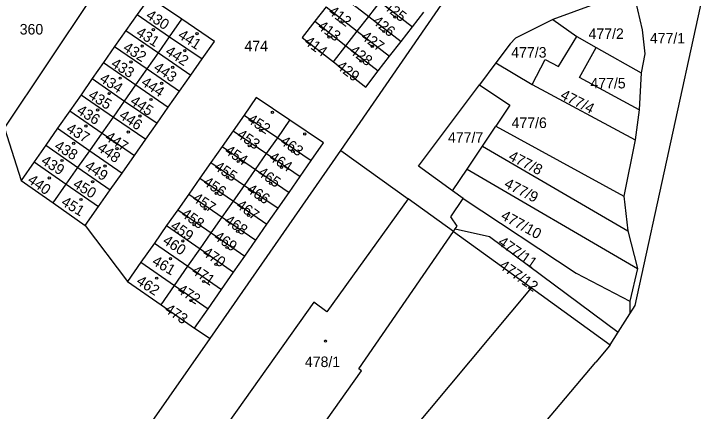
# Model space of a CAD drawing. Extents: x -558358 to -557517, y -1073786 to -1073189.
# Drawn here: x -557909.7 to -557797.9, y -1073407.2 to -1073343.1 of the extents above; entities that cross this region are included whole.
import ezdxf

# ---------------------------------------------------------------- set-up
doc = ezdxf.new("R2010")
doc.units = 0
for name, color, linetype in [('Hranice parcel', 7, 'Continuous'), ('Parcelní čísla', 7, 'Continuous'), ('Značky budov', 7, 'Continuous')]:
    doc.layers.add(name, color=color, linetype=linetype)

msp = doc.modelspace()

# ---------------------------------------------------------------- linework, layer by layer
at = {"layer": 'Hranice parcel'}
for p, q in [((-557911.2, -1073361.51), (-557892.99, -1073334.25)), ((-557809.37, -1073390.13), (-557797.89, -1073337.76)), ((-557809.74, -1073339.14), (-557822.65, -1073343.99)), ((-557857.41, -1073339.54), (-557852.37, -1073343.47)), ((-557852.37, -1073343.47), (-557850.52, -1073341.11)), ((-557850.52, -1073341.11), (-557845.33, -1073345.15)), ((-557859.26, -1073341.9), (-557861.1, -1073344.25)), ((-557859.26, -1073341.9), (-557854.22, -1073345.83)), ((-557845.33, -1073345.15), (-557843.49, -1073342.78)), ((-557889.79, -1073343.18), (-557891.6, -1073345.76)), ((-557889.79, -1073343.18), (-557884.54, -1073346.76)), ((-557884.54, -1073346.76), (-557882.54, -1073343.92)), ((-557854.22, -1073345.83), (-557852.37, -1073343.47)), ((-557852.37, -1073343.47), (-557847.16, -1073347.52)), ((-557861.1, -1073344.25), (-557856.06, -1073348.19)), ((-557822.65, -1073343.99), (-557818.8, -1073346.73)), ((-557891.6, -1073345.76), (-557893.41, -1073348.34)), ((-557891.6, -1073345.76), (-557886.35, -1073349.35)), ((-557856.06, -1073348.19), (-557854.22, -1073345.83)), ((-557854.22, -1073345.83), (-557849, -1073349.9)), ((-557847.16, -1073347.52), (-557845.33, -1073345.15)), ((-557886.35, -1073349.35), (-557884.54, -1073346.76)), ((-557884.54, -1073346.76), (-557879.29, -1073350.34)), ((-557818.8, -1073346.73), (-557815.63, -1073348.5)), ((-557893.41, -1073348.34), (-557895.22, -1073350.93)), ((-557893.41, -1073348.34), (-557888.17, -1073351.94)), ((-557858.09, -1073350.78), (-557856.06, -1073348.19)), ((-557856.06, -1073348.19), (-557850.83, -1073352.27)), ((-557849, -1073349.9), (-557847.16, -1073347.52)), ((-557888.17, -1073351.94), (-557886.35, -1073349.35)), ((-557886.35, -1073349.35), (-557881.11, -1073352.93)), ((-557815.63, -1073348.5), (-557808.41, -1073352.55)), ((-557881.11, -1073352.93), (-557879.29, -1073350.34)), ((-557850.83, -1073352.27), (-557849, -1073349.9)), ((-557895.22, -1073350.93), (-557897.03, -1073353.51)), ((-557895.22, -1073350.93), (-557889.99, -1073354.53)), ((-557831.83, -1073350.97), (-557834.5, -1073354.52)), ((-557831.83, -1073350.97), (-557825.97, -1073354.44)), ((-557889.99, -1073354.53), (-557888.17, -1073351.94)), ((-557888.17, -1073351.94), (-557882.93, -1073355.52)), ((-557808.41, -1073352.55), (-557808.71, -1073358.52)), ((-557897.03, -1073353.51), (-557898.84, -1073356.1)), ((-557897.03, -1073353.51), (-557891.81, -1073357.12)), ((-557882.93, -1073355.52), (-557881.11, -1073352.93)), ((-557891.81, -1073357.12), (-557889.99, -1073354.53)), ((-557889.99, -1073354.53), (-557884.75, -1073358.12)), ((-557825.97, -1073354.44), (-557809.38, -1073363.37)), ((-557898.84, -1073356.1), (-557900.65, -1073358.68)), ((-557898.84, -1073356.1), (-557893.62, -1073359.71)), ((-557884.75, -1073358.12), (-557882.93, -1073355.52)), ((-557893.62, -1073359.71), (-557891.81, -1073357.12)), ((-557891.81, -1073357.12), (-557886.57, -1073360.71)), ((-557886.57, -1073360.71), (-557884.75, -1073358.12)), ((-557900.65, -1073358.68), (-557902.64, -1073361.52)), ((-557900.65, -1073358.68), (-557895.44, -1073362.3)), ((-557872.5, -1073359.38), (-557874.29, -1073361.93)), ((-557872.5, -1073359.38), (-557867.08, -1073363.05)), ((-557808.71, -1073358.52), (-557809.38, -1073363.37)), ((-557895.44, -1073362.3), (-557893.62, -1073359.71)), ((-557893.62, -1073359.71), (-557888.4, -1073363.3)), ((-557867.08, -1073363.05), (-557865.11, -1073360.23)), ((-557911.2, -1073361.51), (-557908.52, -1073369.92)), ((-557902.64, -1073361.52), (-557904.53, -1073364.22)), ((-557902.64, -1073361.52), (-557897.44, -1073365.14)), ((-557888.4, -1073363.3), (-557886.57, -1073360.71)), ((-557834.02, -1073364.39), (-557831.83, -1073361.18)), ((-557831.83, -1073361.18), (-557811.19, -1073372.48)), ((-557897.44, -1073365.14), (-557895.44, -1073362.3)), ((-557895.44, -1073362.3), (-557890.22, -1073365.89)), ((-557874.29, -1073361.93), (-557876.07, -1073364.48)), ((-557874.29, -1073361.93), (-557868.87, -1073365.61)), ((-557890.22, -1073365.89), (-557888.4, -1073363.3)), ((-557868.87, -1073365.61), (-557867.08, -1073363.05)), ((-557867.08, -1073363.05), (-557861.66, -1073366.72)), ((-557809.38, -1073363.37), (-557811.19, -1073372.48)), ((-557904.53, -1073364.22), (-557906.42, -1073366.92)), ((-557904.53, -1073364.22), (-557899.34, -1073367.84)), ((-557899.34, -1073367.84), (-557897.44, -1073365.14)), ((-557897.44, -1073365.14), (-557892.22, -1073368.74)), ((-557877.97, -1073395.43), (-557856.89, -1073365.11)), ((-557876.07, -1073364.48), (-557877.86, -1073367.03)), ((-557876.07, -1073364.48), (-557870.66, -1073368.17)), ((-557856.89, -1073365.11), (-557845.99, -1073372.93)), ((-557836.47, -1073368.11), (-557834.02, -1073364.39)), ((-557834.02, -1073364.39), (-557810.53, -1073378.05)), ((-557892.22, -1073368.74), (-557890.22, -1073365.89)), ((-557870.66, -1073368.17), (-557868.87, -1073365.61)), ((-557868.87, -1073365.61), (-557863.45, -1073369.29)), ((-557906.42, -1073366.92), (-557908.52, -1073369.92)), ((-557906.42, -1073366.92), (-557901.24, -1073370.54)), ((-557877.86, -1073367.03), (-557879.65, -1073369.58)), ((-557877.86, -1073367.03), (-557872.45, -1073370.73)), ((-557863.45, -1073369.29), (-557861.66, -1073366.72)), ((-557901.24, -1073370.54), (-557899.34, -1073367.84)), ((-557899.34, -1073367.84), (-557894.12, -1073371.44)), ((-557872.45, -1073370.73), (-557870.66, -1073368.17)), ((-557870.66, -1073368.17), (-557865.24, -1073371.86)), ((-557838.83, -1073371.62), (-557836.47, -1073368.11)), ((-557836.47, -1073368.11), (-557808.98, -1073384.15)), ((-557894.12, -1073371.44), (-557892.22, -1073368.74)), ((-557879.65, -1073369.58), (-557881.44, -1073372.13)), ((-557879.65, -1073369.58), (-557874.24, -1073373.29)), ((-557865.24, -1073371.86), (-557863.45, -1073369.29)), ((-557908.52, -1073369.92), (-557903.35, -1073373.55)), ((-557903.35, -1073373.55), (-557901.24, -1073370.54)), ((-557901.24, -1073370.54), (-557896.03, -1073374.15)), ((-557874.24, -1073373.29), (-557872.45, -1073370.73)), ((-557872.45, -1073370.73), (-557867.03, -1073374.43)), ((-557896.03, -1073374.15), (-557894.12, -1073371.44)), ((-557867.03, -1073374.43), (-557865.24, -1073371.86)), ((-557837.14, -1073372.84), (-557838.83, -1073371.62)), ((-557881.44, -1073372.13), (-557883.23, -1073374.68)), ((-557881.44, -1073372.13), (-557876.02, -1073375.85)), ((-557838.68, -1073378.19), (-557845.99, -1073372.93)), ((-557837.14, -1073372.84), (-557818.89, -1073384.91)), ((-557811.19, -1073372.48), (-557810.53, -1073378.05)), ((-557903.35, -1073373.55), (-557898.17, -1073377.19)), ((-557876.02, -1073375.85), (-557874.24, -1073373.29)), ((-557874.24, -1073373.29), (-557868.82, -1073377.01)), ((-557898.17, -1073377.19), (-557896.03, -1073374.15)), ((-557883.23, -1073374.68), (-557885.02, -1073377.23)), ((-557883.23, -1073374.68), (-557877.81, -1073378.41)), ((-557868.82, -1073377.01), (-557867.03, -1073374.43)), ((-557877.81, -1073378.41), (-557876.02, -1073375.85)), ((-557876.02, -1073375.85), (-557870.61, -1073379.58)), ((-557898.17, -1073377.19), (-557891.33, -1073386.24)), ((-557885.02, -1073377.23), (-557886.99, -1073380.04)), ((-557885.02, -1073377.23), (-557879.6, -1073380.98)), ((-557870.61, -1073379.58), (-557868.82, -1073377.01)), ((-557879.6, -1073380.98), (-557877.81, -1073378.41)), ((-557877.81, -1073378.41), (-557872.4, -1073382.15)), ((-557838.68, -1073378.19), (-557838.4, -1073377.75)), ((-557838.68, -1073378.19), (-557826.12, -1073387.26)), ((-557810.53, -1073378.05), (-557808.98, -1073384.15)), ((-557872.4, -1073382.15), (-557870.61, -1073379.58)), ((-557886.99, -1073380.04), (-557889.16, -1073383.14)), ((-557886.99, -1073380.04), (-557881.57, -1073383.79)), ((-557881.57, -1073383.79), (-557879.6, -1073380.98)), ((-557879.6, -1073380.98), (-557874.19, -1073384.72)), ((-557874.19, -1073384.72), (-557872.4, -1073382.15)), ((-557889.16, -1073383.14), (-557891.33, -1073386.24)), ((-557889.16, -1073383.14), (-557883.75, -1073386.9)), ((-557883.75, -1073386.9), (-557881.57, -1073383.79)), ((-557881.57, -1073383.79), (-557876.16, -1073387.55)), ((-557808.98, -1073384.15), (-557810.24, -1073389.4)), ((-557876.16, -1073387.55), (-557874.19, -1073384.72)), ((-557818.89, -1073384.91), (-557810.24, -1073389.4)), ((-557891.33, -1073386.24), (-557885.92, -1073390.01)), ((-557885.92, -1073390.01), (-557883.75, -1073386.9)), ((-557883.75, -1073386.9), (-557878.33, -1073390.67)), ((-557826.12, -1073387.26), (-557813.37, -1073396.47)), ((-557878.33, -1073390.67), (-557876.16, -1073387.55)), ((-557810.24, -1073389.4), (-557810.21, -1073391.46)), ((-557885.92, -1073390.01), (-557880.51, -1073393.79)), ((-557880.51, -1073393.79), (-557878.33, -1073390.67)), ((-557810.21, -1073391.46), (-557809.37, -1073390.13)), ((-557812.08, -1073394.43), (-557810.21, -1073391.46)), ((-557880.51, -1073393.79), (-557877.97, -1073395.43)), ((-557813.37, -1073396.47), (-557812.08, -1073394.43)), ((-557813.37, -1073396.47), (-557813.79, -1073396.96)), ((-557813.79, -1073396.96), (-557815.73, -1073399.27)), ((-557834.15, -1073421.11), (-557815.73, -1073399.27))]:
    msp.add_line(p, q, dxfattribs=at)
for points in [[(-558022.09, -1073311.21), (-558020.08, -1073313.87), (-558000.41, -1073328.2), (-557993.92, -1073334.5), (-557986.04, -1073343.93), (-557967.1, -1073369.2), (-557918.24, -1073434.51), (-557914.64, -1073436.24), (-557909.55, -1073436.22), (-557905.05, -1073434.1), (-557902.57, -1073430.65), (-557891.22, -1073414.37), (-557877.97, -1073395.43)], [(-557856.89, -1073365.11), (-557824.85, -1073318.68), (-557819.71, -1073312.13)], [(-557809.74, -1073339.14), (-557808.21, -1073345.61), (-557807.79, -1073349.5), (-557808.41, -1073352.55)], [(-557882.54, -1073343.92), (-557887.8, -1073340.34), (-557889.79, -1073343.18)], [(-557879.29, -1073350.34), (-557877.28, -1073347.5), (-557882.54, -1073343.92)], [(-557861.1, -1073344.25), (-557863.13, -1073346.85), (-557858.09, -1073350.78)], [(-557822.65, -1073343.99), (-557828.66, -1073347), (-557829.52, -1073347.89), (-557831.83, -1073350.97)], [(-557825.97, -1073354.44), (-557823.9, -1073350.44), (-557821.72, -1073351.54), (-557818.8, -1073346.73)], [(-557808.71, -1073358.52), (-557818.34, -1073353.3), (-557815.63, -1073348.5)], [(-557858.09, -1073350.78), (-557852.85, -1073354.88), (-557850.83, -1073352.27)], [(-557838.83, -1073371.62), (-557844.36, -1073367.66), (-557834.5, -1073354.52)], [(-557834.5, -1073354.52), (-557829.59, -1073357.77), (-557831.83, -1073361.18)], [(-557865.11, -1073360.23), (-557870.53, -1073356.57), (-557872.5, -1073359.38)], [(-557861.66, -1073366.72), (-557859.69, -1073363.89), (-557865.11, -1073360.23)], [(-557845.99, -1073372.93), (-557859.12, -1073391.15), (-557861.27, -1073389.6), (-557876.27, -1073410.74), (-557871.76, -1073413.96)], [(-557838.4, -1073377.75), (-557838.12, -1073377.3), (-557839.1, -1073375.8), (-557837.14, -1073372.84)], [(-557866.06, -1073418.25), (-557853.54, -1073400.64), (-557853.96, -1073400.34), (-557838.68, -1073378.19)], [(-557838.4, -1073377.75), (-557832.9, -1073378.99), (-557812.08, -1073394.43)], [(-557861.36, -1073465.07), (-557859.38, -1073443.12), (-557853.44, -1073426.35), (-557845.8, -1073410.81), (-557826.12, -1073387.26)]]:
    msp.add_lwpolyline(points, dxfattribs=at)
at = {"layer": 'Značky budov'}
for centre in [(-557848.17, -1073343.57), (-557856.88, -1073344.34), (-557887.16, -1073345.62), (-557880.1, -1073346.24), (-557849.95, -1073345.91), (-557858.79, -1073346.8), (-557888.96, -1073348.25), (-557851.8, -1073348.3), (-557882.07, -1073349.01), (-557853.64, -1073350.66), (-557890.77, -1073350.82), (-557884.03, -1073351.68), (-557892.51, -1073353.43), (-557885.82, -1073354.26), (-557894.3, -1073355.92), (-557887.55, -1073356.88), (-557896.16, -1073358.56), (-557889.33, -1073359.55), (-557867.93, -1073358.96), (-557898.05, -1073361.16), (-557869.83, -1073361.84), (-557891.21, -1073362.13), (-557862.71, -1073362.44), (-557900.02, -1073363.95), (-557893.03, -1073364.8), (-557871.67, -1073364.36), (-557864.65, -1073365.25), (-557901.91, -1073366.72), (-557873.46, -1073366.87), (-557894.96, -1073367.61), (-557866.46, -1073367.83), (-557903.97, -1073369.53), (-557875.18, -1073369.44), (-557896.97, -1073370.15), (-557868.22, -1073370.41), (-557877.01, -1073372.01), (-557898.85, -1073373.01), (-557869.95, -1073373.03), (-557878.79, -1073374.53), (-557871.78, -1073375.57), (-557880.58, -1073377.07), (-557873.54, -1073378.14), (-557882.4, -1073379.7), (-557875.27, -1073380.75), (-557884.39, -1073382.56), (-557877.05, -1073383.46), (-557886.62, -1073385.7), (-557879.05, -1073386.25), (-557881.11, -1073389.32), (-557859.37, -1073395.86)]:
    msp.add_circle(centre, 0.175, dxfattribs=at)

# ---------------------------------------------------------------- texts
at = {"layer": 'Parcelní čísla'}
for s, rotation, p in [('425', 322, (-557850.11, -1073342.12)), ('430', 327, (-557888.49, -1073343.66)), ('412', 323, (-557859.02, -1073342.96)), ('426', 321, (-557851.91, -1073344.49)), ('413', 324, (-557860.76, -1073345.36)), ('431', 328, (-557890.08, -1073346.47)), ('441', 327, (-557883.32, -1073346.85)), ('427', 324, (-557853.74, -1073347.03)), ('414', 324, (-557862.92, -1073347.85)), ('432', 328, (-557892.19, -1073348.9)), ('428', 323, (-557855.61, -1073349.29)), ('442', 327, (-557885.36, -1073349.49)), ('433', 328, (-557894.13, -1073351.48)), ('443', 326, (-557887.26, -1073352.08)), ('429', 323, (-557857.71, -1073351.8)), ('434', 327, (-557895.98, -1073353.89)), ('444', 326, (-557889.27, -1073354.46)), ('435', 328, (-557897.79, -1073356.58)), ('477/4', 333, (-557821.57, -1073356.66)), ('445', 326, (-557891.04, -1073357.5)), ('436', 328, (-557899.67, -1073359.04)), ('446', 326, (-557892.82, -1073359.8)), ('452', 327, (-557872.13, -1073360.48)), ('437', 329, (-557901.36, -1073362)), ('447', 327, (-557895.11, -1073363.31)), ('453', 326, (-557873.82, -1073362.91)), ('438', 329, (-557903.28, -1073364.79)), ('463', 325, (-557866.82, -1073363.96)), ('448', 325, (-557896.35, -1073365.03)), ('454', 326, (-557875.78, -1073365.49)), ('439', 328, (-557905.42, -1073367.16)), ('464', 327, (-557868.6, -1073366.58)), ('477/8', 333, (-557829.94, -1073366.55)), ('449', 326, (-557898.38, -1073367.98)), ('455', 326, (-557877.48, -1073368.08)), ('465', 325, (-557870.46, -1073369)), ('440', 325, (-557907.6, -1073370.19)), ('456', 326, (-557879.26, -1073370.56)), ('450', 329, (-557900.28, -1073370.96)), ('466', 326, (-557872.22, -1073371.73)), ('477/9', 333, (-557830.64, -1073370.98)), ('451', 329, (-557902.18, -1073373.84)), ('457', 327, (-557880.97, -1073373.18)), ('467', 324, (-557873.92, -1073374.23)), ('458', 325, (-557882.8, -1073375.67)), ('477/10', 331, (-557831.18, -1073376.1)), ('468', 326, (-557875.81, -1073376.75)), ('459', 325, (-557884.54, -1073377.63)), ('469', 326, (-557877.52, -1073379.37)), ('460', 327, (-557885.79, -1073380.03)), ('477/11', 325, (-557831.64, -1073380.2)), ('470', 326, (-557879.37, -1073381.93)), ('461', 330, (-557887.5, -1073383.42)), ('477/12', 325, (-557831.47, -1073384)), ('471', 326, (-557881.11, -1073384.86)), ('462', 327, (-557890.05, -1073386.55)), ('472', 327, (-557883.44, -1073387.95)), ('473', 326, (-557885.47, -1073391.09))]:
    msp.add_text(s, height=1.7, rotation=rotation, dxfattribs=at).set_placement(p)
for s, p in [('360', (-557908.74, -1073346.39)), ('477/2', (-557816.88, -1073347.11)), ('477/1', (-557806.98, -1073347.84)), ('474', (-557872.44, -1073349.09)), ('477/3', (-557829.36, -1073350.12)), ('477/5', (-557816.58, -1073355.09)), ('477/6', (-557829.31, -1073361.48)), ('477/7', (-557839.58, -1073363.85)), ('478/1', (-557862.68, -1073400.05))]:
    msp.add_text(s, height=1.7, dxfattribs=at).set_placement(p)

doc.saveas('drawing.dxf')
